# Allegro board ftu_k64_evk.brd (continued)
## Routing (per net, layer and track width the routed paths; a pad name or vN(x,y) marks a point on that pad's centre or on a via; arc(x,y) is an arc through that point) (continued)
U2_IN_N: length 36.9
  TOP w0.178: v1(34.67,52.43) 35.29,52.43 R43.2 36.49,51.23 C45.2 31.27,49.37 PT2.3 28.16,48.02 26.53,46.4 26.53,44.56 R44.2 26.58,44.53 D16.A ; R39.1 39.16,43.49 39.65,43 39.65,41.89 v1(39.75,41.78)
  BOTTOM w0.178: v1(34.67,52.43) 34.92,52.68 37.28,52.68 38.86,51.1 38.86,44.04 39.75,43.15 v1(39.75,41.78)
U2P_OUT: length 51.1
  TOP w0.305: U1.27 65.17,57.75 65.74,57.19 v1(65.74,56.52) ; C42.1 33.6,35.36 R38.2 33.58,37.13 v1(32.38,37.13)
  BOTTOM w0.305: v1(65.74,56.52) 64.92,57.33 53.89,57.33 43.91,47.35 43.91,40.86 40.18,37.13 v1(32.38,37.13)
U3_IN_N: length 47.5
  TOP w0.178: C52.2 38.17,32.41 R54.2 ; C52.2 36.23,31.94 C54.2 ; C52.2 36.23,33.23 v1(36.45,33.45) ; v1(54.33,55.5) 54.39,55.5 55.14,56.25 U1.30
  BOTTOM w0.178: v1(54.33,55.5) 54.02,55.5 45.49,46.97 45.49,40.54 38.84,33.88 36.88,33.88 v1(36.45,33.45)
U3_IN_P: length 49.3
  TOP w0.178: C52.1 35.28,31.99 35.28,31 C50.1 ; C52.1 35.28,32.83 35.28,33.45 v1(35.36,33.53) ; C52.1 R49.2 ; U1.29 63.6,56.75 63.56,56.72 54.83,56.72 v1(54.38,56.26)
  BOTTOM w0.178: v1(54.38,56.26) 54.17,56.26 45.19,47.28 45.19,40.67 38.84,34.32 36.14,34.32 v1(35.36,33.53)
UART1_RX: length 85.6
  TOP w0.127: v1(87.24,69.42) 86.91,69.75 U1.106 ; v1(96.24,68.81) 96.24,68.17 104.44,59.97 108.03,59.97 116.71,51.29 116.71,33.38 TP22.1 119.43,30.66 119.43,28.77 121.1,27.09 139.36,27.09 140.26,28 R140.1
  BOTTOM w0.127: v1(96.24,68.81) 95.83,68.4 88.26,68.4 v1(87.24,69.42)
UART1_TX: length 111.9
  TOP w0.127: R136.1 141.35,29.07 141.35,27.89 140.3,26.84 120.67,26.84 TP21.1 116.45,31.05 116.45,51.19 108,59.64 104.17,59.64 96.73,67.08 v1(96.18,67.08) ; U1.1 65.05,70.75 66.44,69.36 66.44,67.41 v1(66.09,67.06)
  BOTTOM w0.127: v1(96.18,67.08) 93.16,67.08 93.14,67.06 v1(66.09,67.06)
USB_5V: length 4.7
  TOP w0.305: U1.22 62.15,60.25 60.52,58.62 R3.1
USB_5V_HOST: length 3.1
  TOP w0.508: C80.1 142.26,113.62 U18.5
USB_EN: length 4
  TOP w0.508: TP20.1 135.16,107.49 R111.2 133.59,109.59 U17.3
USB_HOST_D_N: length 108
  TOP w0.127: v1(136.93,117.55) 137.05,117.43 L14.1 ; R10.2 58.19,62.99 57.52,63.65 56.99,63.65 v1(56.71,63.37)
  BOTTOM w0.127: v1(136.93,117.55) 136.58,117.55 136.24,117.21 136.24,114.92 107.3,85.98 107.3,84.95 106.89,84.54 100.79,84.54 85.01,68.76 62.99,68.76 57.91,63.68 57.03,63.68 56.96,63.61 v1(56.71,63.37)
USB_HOST_D_P: length 108
  TOP w0.127: L14.4 137.77,118.34 136.9,118.34 v1(136.88,118.31) ; R9.2 58.19,64.36 57.75,63.93 56.94,63.93 v1(56.74,64.14)
  BOTTOM w0.127: v1(56.74,64.14) 56.9,63.96 57.79,63.96 62.87,69.04 84.89,69.04 100.68,84.82 106.77,84.82 107.02,85.07 107.02,86.09 135.96,115.04 135.96,117.32 136.75,118.11 136.75,118.18 v1(136.88,118.31)
USB_HOST_VBUS: length 14.1
  TOP w0.508: C84.1 131.68,112.26 U17.6
  TOP w0.762: C84.1 134.55,114.26 135.61,113.21 135.61,111.99 138.22,109.37 L12.1
VOUT33: length 6.1
  TOP w0.305: C18.1 61.08,60.05 61.79,60.75 U1.21
  TOP w0.508: C17.1 C18.1
VREF_ADC: length 16.1
  TOP w0.508: C123.1 42.14,19.38 R162.1 42.14,22.17 L26.2 41.68,24.32 41.68,27.64 42.82,28.78 L10.2 44.01,28.83 44.01,30.26 L9.2 43.97,31.71 L27.2
VREF_ADC_HALF: length 29.4
  TOP w0.508: C119.1 v1(44.35,17.37) ; C119.1 v1(44.35,15.57) 44.35,14.68 C122.1 44.94,14.63 45.48,15.17 U32.7 ; C119.1 44.39,16.44 U32.6 ; v1(42.72,42.09) 42.72,42.37 43.57,43.21 R35.1 ; v1(53.65,14.43) 54.14,14.43 C120.1 54.51,15.17 U32.2 ; U6.5 v1(43,54.59) ; U32.1 52.62,13.9 53.09,13.44 C121.1 v1(54.67,12.55) ; L26.1 v1(45.29,23.01) ; R53.1 33.09,11.15 v1(33.43,10.82) ; U6.3 45.54,54.74 v1(45.33,54.53) ; R51.2 v1(35.43,10.87)
  TOP w1.016: R32.1 v1(12.89,109.52) ; TP44.1 v1(5.02,133.96) ; R30.2 v1(13.12,106.61)
VREF_HALF: length 21.9
  TOP w0.508: C123.2 45.52,18.54 46.33,17.73 46.65,17.73 U32.5 ; U32.3 53.48,16.44 53.62,16.59 C124.1
  TOP w0.762: C123.2 44.36,18.83 45.39,19.86 R162.2 46.23,19.86 R163.1 48.16,20.17 49.25,21.26 52.81,21.26 54.72,19.35 C124.1
VREF_OUT: length 38.9
  TOP w0.305: U1.37 66.13,51.3
  TOP w0.762: L9.1 58.17,30.3 59.86,32 59.86,42.24 61.72,44.09 C12.1 61.72,47.45 C11.1 61.77,48.45 62.22,48.9 62.22,50.09 63.44,51.3 66.13,51.3
VREFH: length 44.8
  TOP w0.305: U1.32 62.61,55.25 61.92,54.56 61.92,52.3 61.26,51.64 59.18,51.64 58.87,51.95 L1.1
  TOP w0.508: L1.1 57.93,52.4 57.6,52.07 57.6,51.16 57.96,50.8 C14.1 C13.1 58.95,33.27 57.04,31.37 45.69,31.37 L27.1
WAKE: length 7.3
  TOP w0.127: U12.22 108.14,97.7 107.75,98.08 R91.2 109.1,99.69 R81.1 110.49,99.7 R88.2
WDOG: length 48.8
  TOP w0.127: R147.2 113.44,25.01 R145.2 106.02,25.07 95.44,35.65 95.44,48.61 93.14,50.9 90.27,50.9 86.92,54.25 U1.75
WIFI/LCD_GPIO1: length 106.6
  TOP w0.127: v1(75.86,149.02) 73.96,147.12 73.96,140.72 75.84,138.84 75.84,113.83 62.72,100.71 62.72,78.03 56.51,71.82 56.51,68.7 57.42,67.79 62.47,67.79 63.52,66.75 U1.9
  BOTTOM w0.127: J21.13 78.96,154.1 78.96,152.12 v1(75.86,149.02)
WIFI/LCD_GPIO2: length 109.4
  TOP w0.127: J21.15 77.07,156.26 75.51,156.26 75.13,155.88 75.13,148.67 73.71,147.24 73.71,140.61 75.59,138.73 75.59,113.93 62.47,100.81 62.47,78.14 56.26,71.93 56.26,68.59 57.31,67.54 62.37,67.54 63.66,66.25 U1.10
WIFI/LCD_GPIO3: length 107.2
  TOP w0.127: U1.15 65.96,63.75 66.7,64.49 66.7,69.6 64.24,72.06 64.24,100.08 77.36,113.19 77.36,135.74 83.43,141.81 83.43,146.63 81.27,148.79 78.02,148.79 76.96,149.86 76.96,154.38 J21.17
WIFI/LCD_GPIO4: length 92.1
  TOP w0.127: U1.139 68.88,77.91 67.69,79.11 67.69,100.11 79.34,111.77 79.34,134.72 v1(79.65,135.03) ; J21.19 72.87,154 72.87,140.46 v1(74.9,138.43)
  BOTTOM w0.127: v1(74.9,138.43) 78.3,135.03 v1(79.65,135.03)
WIFI/LCD_PWR_CNTL: length 71.4
  TOP w0.127: v1(85.03,128.24) 85.03,117.1 67.94,100.01 67.94,79.91 69.34,78.51 69.34,74.37 70.38,73.33 U1.136 ; v1(91.16,129.87) 91.29,129.74 R153.2
  BOTTOM w0.127: v1(91.16,129.87) 86.66,129.87 v1(85.03,128.24)
N16756265: length 3
  TOP w0.127: R65.1 T1.10
N16756269: length 3.3
  TOP w0.127: R66.1 137.7,69.23 137.21,68.73 T1.15
N16757442: length 16.4
  TOP w0.305: D11.A 142.6,39.2 142.2,38.8 R135.2 ; D11.A 146.72,40.79 DN2.1 ; D11.A 147.47,36.86 147.47,34.98 148.67,33.77 J16.2
N16757516: length 15.9
  TOP w0.305: D10.A 146.29,28.47 DN1.1 ; J16.3 146.85,31.03 DN1.1 ; DN1.1 145.1,31.65 145.1,32.38 144.5,32.99 142.98,32.99 R139.2
N16758787: length 3.4
  TOP w0.305: U28.1 125.83,39.06 125.32,39.57 C93.1
N16758791: length 5.4
  TOP w0.305: U28.3 125.71,37.76 124.81,38.66 123.54,38.66 122.74,39.46 C93.2
N16758795: length 3.5
  TOP w0.305: U28.4 125.5,37.11 124.91,37.69 C92.1
N16758815: length 5.2
  TOP w0.305: U28.5 125.18,36.46 124.81,36.83 123.44,36.83 122.69,37.58 C92.2
N16758819: length 3.4
  TOP w0.305: C91.2 124.32,35.81 U28.6
N16758823: length 4.8
  TOP w0.305: R135.1 137.88,38.8 136.84,37.76 U28.14
N16758837: length 7
  TOP w0.305: R134.2 138.6,31.56 136.37,33.79 136.37,35.28 135.84,35.81 U28.11
N16758843: length 6.7
  TOP w0.305: U28.12 135.8,36.46 136.8,35.46 136.8,33.97 137.81,32.96 R138.2
N16758849: length 4.8
  TOP w0.305: C89.1 128.56,40.37 129.1,39.83 129.1,38.63 128.88,38.41 U28.2
N16758873: length 5.1
  TOP w0.305: R139.1 137.88,35.38 136.15,37.11 U28.13
N16759319: length 2.5
  TOP w0.127: R25.1 80.22,143.73 U5.7
N16772440: length 9.4
  TOP w0.508: R28.2 48.08,56.88 U6.1 ; R28.2 48.51,60.34 R27.1 ; R28.2 51.75,60.54 D3.A
N16775214: length 11.3
  TOP w0.508: D4.A 40.66,63.3 39.04,61.68 R31.1 37.12,60.09 R33.2 38.04,58.29 38.7,58.29 40.46,56.53 U6.7
N16775930: length 19.6
  TOP w0.305: R38.1 35.2,38.44 D5.A 35.2,40.49 35.2,42.46 R40.2 34.85,44.79 34.85,47.98 35.2,48.34 38.91,48.34 40.46,49.89 U6.8
N16775968: length 6.3
  TOP w0.305: U6.10 43,49.02 43.57,48.46 R35.2 43.53,46.77 R37.2
N16775998: length 7.5
  TOP w0.305: U6.9 41.73,49.86 39.8,47.93 39.8,47.79 R39.2 38.71,46.7 R40.1
N16783367: length 15.4
  TOP w0.508: C46.2 49.05,39.46 R45.2 49.35,42.38 R47.1 49.41,44.2 C47.1 48.8,45.86 45.54,49.12 U6.12
N16785222: length 16.5
  TOP w0.762: v1(39.85,27.15) 39.77,27.23 L8.1
  BOTTOM w1.016: PT3.3 39.85,26.22 v1(39.85,27.15)
N16786136: length 2.5
  TOP w0.178: L8.2 39.77,32.38 R54.1
N16786139: length 1.8
  TOP w0.178: R49.1 L7.2
N16788483: length 15.2
  TOP w0.508: U6.13 46.81,51.54 47.24,51.96 47.95,51.96 48.08,51.84 U6.14 48.08,48.73 R46.1 52.56,45.2 53.69,44.07 D6.A
N16795804: length 1.8
  TOP w0.762: R157.1 129.52,135.55 D12.A
N16798051: length 3.9
  TOP w0.508: U17.5 132.65,111.47 132.26,111.09 C83.1
N16806806: length 4
  TOP w0.127: C77.1 118.94,80.21 R96.1 117.16,80.57 Y2.1
N16812858: length 3.2
  TOP w0.127: R2.2 81.22,49.12 81.88,49.78 U1.68
N16812861: length 3.1
  TOP w0.127: R4.2 82.38,48.52 U1.69
N16826797: length 12
  TOP w0.305: U22.4 30.17,119.98 30.17,123.06 30.45,123.34 R114.2 ; U21.2 30.28,124.12 R114.2 ; U21.3 31.55,123.83 R114.2
N16826898: length 8.7
  TOP w0.305: U23.4 34.55,122.36 33.62,123.29 R118.2 32.82,123.3 U21.4
N16826947: length 13.1
  TOP w0.508: R124.1 25.15,135.21 v1(25.12,135.18)
  BOTTOM w0.508: J12.1 36.16,134.8 25.5,134.8 v1(25.12,135.18)
N16841183: length 16.8
  TOP w0.508: R132.1 43.01,131.33 44.47,129.87 52.8,129.87 54.01,131.08 54.01,132.62 J14.1
N16842812: length 2.3
  TOP w0.127: R115.1 31.1,109.18 U22.2
N16843774: length 2.4
  TOP w0.127: R119.1 36.76,110.42 U23.2
N16843986: length 8
  TOP w0.305: U19.2 26.14,121.68 R113.2
N16846359: length 2.7
  TOP w0.305: R113.1 29.32,124.28 29.01,124.59 U21.1
N16848477: length 2.8
  TOP w0.127: U26.2 49.07,108.61 R125.1
N16848509: length 13.2
  TOP w0.305: R123.2 48.71,123.72 48.71,124.89 48.47,125.14 U25.2 ; R123.2 48.2,123.7 47.98,123.47 47.98,119.74 U26.4 ; R123.2 49.74,124.7 U25.3
N16848511: length 2.3
  TOP w0.127: R131.1 55.11,109.21 U27.2
N16848567: length 9.8
  TOP w0.305: U27.4 52.57,121.79 50.77,123.6 R130.2 50.36,124.72 51.01,125.36 U25.4
N16848581: length 9.2
  TOP w0.305: R121.2 42.79,122.12 40.68,120.01 U24.2
N16848643: length 3
  TOP w0.305: U25.1 47.2,125.11 47.25,125.06 R121.1
N16852593: length 4.7
  TOP w0.127: R143.2 116.69,17.54 117.64,18.48 U29.8
N16852608: length 21
  TOP w0.127: SW3.4 SW3.3 125.78,17.73 R142.2 125.84,17.79 C95.1 124.71,19.25 123.91,20.06 U29.1 122.03,20.06 121.37,19.39 J17.1
N16852627: length 2.9
  TOP w0.127: U29.7 116.77,21.33 116.11,21.98 R146.1
N16852920: length 3
  TOP w0.127: R147.1 115.68,23.48 116.56,22.6 U29.6
N16858143: length 6.2
  TOP w0.127: R67.1 146.29,58.08 P1.11
N16858278: length 7.3
  TOP w0.127: R68.1 143.11,72.73 P1.9
N16861702: length 3.2
  TOP w0.127: T2.10 137.05,89.53 137.3,89.29 R92.1
N16861704: length 3
  TOP w0.127: T2.15 135.57,95.79 R93.1
N16871213: length 6.4
  TOP w0.305: L22.1 103.89,129.93 Q3.2 102.35,127.63 L20.1 100.14,127.53 R149.1
N16871247: length 4.1
  TOP w0.305: R153.1 92.68,127.52 R155.1 94.11,127.54 Q5.1
N16871250: length 9.4
  TOP w0.305: C100.2 98.56,128.5 98.51,128.45 R149.2 ; C100.2 97.61,129.95 96.82,130.73 96.82,132.21 R151.1 ; C100.2 98.58,129.93 Q3.1
N16871668: length 2.1
  TOP w0.305: Q5.3 94.14,132.47 R151.2
N16872241: length 4.7
  TOP w0.305: R154.1 110.44,129.71 Q6.1 110.44,129.7 R156.1
N16872243: length 9.7
  TOP w0.305: R150.2 116.54,129.07 Q4.1 114.69,129.24 C102.2 113.9,129.53 113.6,129.83 113.6,132.03 R152.1
N16872250: length 5.2
  TOP w0.305: R150.1 118.14,129.11 Q4.2 120.08,129.24 L21.1 121.55,129.24 L23.1
N16872280: length 2.5
  TOP w0.305: Q6.3 110.15,133.14 R152.2
N16877055: length 2.9
  TOP w0.508: U30.1 115.7,116.4 R159.2
N16877530: length 3.8
  TOP w0.508: R160.2 122.01,116.78 119.76,114.54 U30.8
N16877846: length 1.6
  TOP w0.508: C111.1 123.59,116.94 R160.1
N16878713: length 4.7
  TOP w0.508: U30.7 120.75,113.27 121.39,113.9 R158.1 122.14,113.97 R161.2
N16899253: length 7
  TOP w0.305: R97.1 115.99,83.32 114.09,85.22 U12.1
N16906260: length 7
  TOP w0.127: R94.1 144.43,86.98 P2.11
N16913941: length 3.7
  TOP w0.127: R84.2 103.69,90.21 104.35,90.87 U12.31
N16913953: length 4
  TOP w0.127: R85.2 103.34,93.23 104.69,91.87 U12.29
N16913968: length 4.3
  TOP w0.127: R86.2 102.45,94.57 104.65,92.37 U12.28
N16913982: length 5.4
  TOP w0.127: R87.2 102.83,95.97 103.32,95.48 103.32,94.28 104.73,92.87 U12.27
N16913996: length 5.9
  TOP w0.127: R89.2 103.73,95.84 103.73,94.56 104.91,93.37 U12.26
N16917794: length 5.5
  TOP w0.127: U1.74 86.78,53.75 89.34,51.19 R11.1
N16918817: length 6.4
  TOP w0.127: R12.1 68.36,44.88 68.36,49.91 68.38,49.93 U1.41
N16919212: length 2.6
  TOP w0.127: Y1.1 87.65,43.91 R16.2
N16919504: length 2.4
  TOP w0.127: Y1.3 92.73,47.66 R18.1
N16920348: length 5.2
  TOP w0.127: R9.1 62.92,61.75 U1.19
N16920352: length 4.8
  TOP w0.127: U1.20 62.05,61.25 R10.1
N16922932: length 1.6
  TOP w0.305: R99.1 102.51,78.49 D8.C
N16922934: length 2.3
  TOP w0.305: R99.2 104.09,77.81 Q1.3
N16922936: length 1.9
  TOP w0.305: R101.1 100.09,74.43 Q1.1
N16922944: length 2.2
  TOP w0.305: Q2.3 98.18,77.59 R100.2
N16922946: length 1.7
  TOP w0.305: D9.C 96.58,80.12 R100.1
N16922998: length 2.2
  TOP w0.127: R106.1 60.88,109.09 U15.2
N16923008: length 51.9
  TOP w0.305: J8.2 48.93,155.19 48.25,154.5 R104.2 48.91,152.5 55.8,152.5 61.13,147.17 61.13,138.05 56.84,133.76 56.84,122.79 58.34,121.28 U15.4
N16923020: length 44.4
  TOP w0.305: U15.3 60.88,120.95 58.11,123.72 58.11,134.16 61.56,137.62 61.56,148.06 55.28,154.34 R108.1 54.4,154.53 53.75,155.19 J8.1
N16923032: length 3.3
  TOP w0.127: R105.1 65.66,108.54 66.65,109.52 U16.2
N16923042: length 43.7
  TOP w0.305: U16.4 64.11,119.83 58.54,125.4 58.54,132.41 62.2,136.07 62.2,148.97 58.86,152.31 R103.2 60.34,154.25 J9.2
N16923054: length 44.3
  TOP w0.305: U16.3 66.65,118.87 59.66,125.86 59.66,132.11 62.66,135.1 62.66,146.81 66.15,150.31 R107.1 65.43,154.37 64.75,155.06 J9.1
N16935990: length 1.7
  TOP w0.508: R34.1 16.57,116.64 L6.2
N16935992: length 1.7
  TOP w0.508: L5.2 18.09,99.66 R29.1
N16963015: length 2.5
  TOP w0.127: TP12.1 99.41,97.37 R89.1
N16963035: length 2.3
  TOP w0.127: R84.1 99.23,90.21 TP9.1
N16963490: length 2.6
  TOP w0.127: TP10.1 100.12,93.23 R85.1
N16963499: length 2.4
  TOP w0.127: R86.1 99.82,93.74 TP8.1
N16963508: length 2.2
  TOP w0.127: TP11.1 98.65,95.97 R87.1
N16964483: length 6.7
  TOP w0.127: R143.1 113.32,16.77 113.81,16.28 118.28,16.28 J17.2
N16992640: length 4.7
  TOP w0.127: R13.2 60.68,71.5 62.43,69.75 U1.3
N16997663: length 8.6
  TOP w0.305: U28.9 134.28,31.38 136.89,28.77 R140.2
N16997666: length 7.5
  TOP w0.305: U28.10 135.42,35.16 135.73,34.85 135.73,33.08 R136.2
N17002202: length 4.1
  TOP w0.127: TP18.1 69.31,9.28 J10.15
N17002209: length 9
  TOP w0.127: TP17.1 75.61,9.26 73.6,9.26 72.28,7.94 72.28,6.36 J10.14
N17002232: length 7
  TOP w0.127: TP19.1 70.33,8.14 70.33,6.4 J10.16
N17002285: length 2.7
  TOP w0.127: TP27.1 109.92,155.26 J22.11
N17002298: length 2.7
  TOP w0.127: TP28.1 107.96,155.21 J22.13
N17002307: length 2.7
  TOP w0.127: J22.15 105.93,155.25 TP30.1
N17009409: length 4.4
  TOP w0.508: U7.7 57.67,6.64 R55.1 57.82,6.49 57.82,4.62 D7.A
N17012939: length 5.8
  TOP w0.305: U28.7 125.45,35.16 123.64,33.35 R137.1
N17012953: length 9
  TOP w0.305: U28.8 127.32,29.66 126.24,28.58 R141.1
N17025356: length 4.5
  TOP w0.305: U20.4 62.94,128.12 L15.1
N17038152: length 2.5
  TOP w0.127: U2.8 108.79,42.95 R14.1
N17038155: length 2.5
  TOP w0.127: U2.7 110.06,43.23 R15.1
N17041648: length 2.9
  TOP w0.127: TP31.1 78.1,150.44 J21.16
N17041650: length 2.9
  TOP w0.127: J21.14 80.1,150.37 TP29.1
N17041652: length 2.9
  TOP w0.127: J21.10 84.1,151.75 84.06,151.71 TP26.1
N17041654: length 2.8
  TOP w0.127: TP25.1 92.1,150.49 J21.2
N17042189: length 3.5
  TOP w0.127: R148.1 105.97,153.2 J22.16
N17042264: length 2.6
  TOP w0.127: J22.17 104,155.24 TP34.1
N17042273: length 2.6
  TOP w0.127: J22.19 101.97,155.21 TP35.1
N17042288: length 2.8
  TOP w0.127: J22.18 103.96,151.91 103.92,151.87 TP36.1
N17042303: length 2.8
  TOP w0.127: J22.20 101.96,151.96 101.89,151.88 TP37.1
N17042405: length 2.8
  TOP w0.127: J21.18 76.1,150.43 TP38.1
N17042414: length 2.8
  TOP w0.127: J21.20 74.05,153.19 TP39.1
N17045351: length 3.8
  TOP w0.127: TP40.1 67.31,9.97 J10.17
N17045355: length 4.8
  TOP w0.127: J10.19 62.06,10.63 TP41.1
N17045369: length 6.1
  TOP w0.127: J10.18 68.3,6.37 68.3,10.43 TP42.1
N17045378: length 6.6
  TOP w0.127: J10.20 66.19,6.26 66.19,8.83 TP43.1
N17061950: length 1.9
  TOP w0.305: Q2.1 94.57,74.48 R102.1
N17108951: length 28.3
  TOP w0.508: C65.1 147.17,75.2 v1(147.04,75.06) ; R66.2 140.24,69.27 v1(141.24,69.27) ; R65.2 v1(140.18,61.16)
  BOTTOM w0.508: v1(147.04,75.06) v1(141.24,69.27) 136.16,69.27 135.7,68.81 135.7,63.81 138.35,61.16 v1(140.18,61.16)
N17109053: length 28.6
  TOP w0.508: v1(146.86,101.63) 146.97,101.74 C76.1 ; R93.2 v1(140.05,96.68)
  TOP w0.762: R92.2 v1(141.31,89.29)
  BOTTOM w0.508: v1(141.31,89.29) 137.02,89.29 135.66,90.65 135.66,95.83 136.5,96.68 v1(140.05,96.68) 141.91,96.68 v1(146.86,101.63)
N17166355: length 3
  TOP w0.305: R75.1 R76.1 120.44,91.66 C125.1
N17166431: length 3.2
  TOP w0.305: C126.1 120.73,88.92 R78.1 118.9,88.89 R77.1
N17167419: length 5.3
  TOP w0.127: J10.13 73.71,9.78 74.19,9.78 TP45.1
N17171737: length 4.8
  TOP w0.127: U1.38 66.88,50.65 66.63,50.4 64.44,50.4 TP46.1
N17171740: length 3.3
  TOP w0.127: TP47.1 66.14,50.15 66.84,50.15 67.38,50.68 U1.39
N17171751: length 4.2
  TOP w0.127: U1.35 62.87,53.75 62.26,53.14 62.26,51.47 TP48.1
N17171755: length 2.3
  TOP w0.127: TP49.1 62.9,57.59 63.56,58.25 U1.26

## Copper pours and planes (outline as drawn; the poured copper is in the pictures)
5V_DC_JACK on TOP: 144.7,144.88 148.31,144.88 149.3,143.89 149.3,137.54 147.57,135.81 140.08,135.81 137.21,138.68 135.78,138.68 135.38,139.09 135.38,141.15 135.94,141.71 141.52,141.71
5V_IN on TOP: 131.31,145.01 138.58,145.01 138.98,144.6 138.98,142.65 138.42,142.09 135.63,142.09 134.84,141.3 134.84,138.71 135.17,138.38 135.17,137.06 135.15,137.03 132.38,137.03 132.1,136.75 130.78,136.75 130.65,136.88 130.65,144.35
AGND on BOTTOM: 0.94,159.05 66.16,159.05 67.11,158.11 67.11,117.66 66.24,116.8 22.85,116.8 21.84,117.81 21.84,133.95 16.79,139 1.05,139 0.8,139.24 0.8,158.92
AGND on GND: 16.64,138.91 0.76,138.91 0.76,159.24 67.23,159.24 67.23,120.96 67.33,120.85 67.33,117.68 66.24,116.59 21.89,116.59 21.89,133.66
GND on TOP: 130.63,152.63 148.03,152.63 154.27,146.38 154.27,138.84 153.46,138.02 151.96,138.02 150.59,139.4 150.59,144.48 149.4,145.67 144.17,145.67 141.47,142.98 140.2,142.98 139.64,143.54 139.64,144.78 138.15,146.28 130.96,146.28 128.87,148.36 128.87,150.88
GND on TOP: 113.15,113.74 114.8,113.74 115.41,114.35 117.7,114.35 117.83,114.22 117.83,107.9 117.37,107.44 113.13,107.44 112.47,108.1 112.47,110.57 112.95,111.05 114.8,111.05 115.11,111.35 115.11,112.62 114.78,112.95 113.08,112.95 113,113.03 113,113.59
GND on BOTTOM: 67.97,158.98 148.89,158.98 150.33,157.54 150.33,152.6 154.06,148.87 154.06,139.18 153.38,138.51 148.22,138.51 145.51,135.8 145.51,105.19 141.74,101.42 128.77,101.42 126.96,99.61 126.96,59.13 127.42,58.68 136.24,58.68 136.84,59.28 140.76,59.28 147.85,52.19 147.85,36.66 151.24,33.27 151.24,23.85 148.45,21.06 148.45,15.52 150.22,13.75 150.22,10.2 149.58,9.56 148.33,9.56 148.3,9.6 146.71,9.6 142.19,5.08 88.33,5.08 86.33,7.07 86.33,11.3 86.71,11.67 86.71,20.84 78.6,28.94 78.6,47.6 77.13,49.06 69.82,49.06 68.05,50.84 68.05,57.96 65.26,60.75 61.61,60.75 60.7,59.84 56.93,59.84 47.39,69.38 47.39,90.3 48.07,90.98 52.1,90.98 52.97,91.84 52.97,95.42 51.05,97.35 46.79,97.35 42.49,101.64 28.36,101.64 22.06,107.94 22.06,115.06 22.59,115.59 66.77,115.59 67.97,116.8 ; 19 cut-outs
GND on GND: 63.04,0.76 63.04,47.39 63.78,48.13 65.53,48.13 67.94,50.54 67.94,57.79 65.43,60.3 62.3,60.3 61.43,59.44 57.05,59.44 47.19,69.29 47.19,96.8 42.7,101.3 28.4,101.3 21.84,107.85 21.84,116.08 66.92,116.08 67.92,117.07 67.92,159.01 68.15,159.24 159.24,159.24 159.24,0.76
GND_EARTH on TOP: 151.73,158.47 157.58,158.47 159.05,157 159.05,2.69 157.47,1.12 153.49,1.12 153.46,1.14 1.99,1.14 0.89,2.24 0.89,5.86 2.4,7.37 5.36,7.37 8.74,4 11.9,4 12.6,3.29 83.61,3.29 84.77,4.45 123.88,4.45 124.55,3.78 148.65,3.78 152.29,7.43 152.29,13.46 149.32,16.43 149.32,20.52 154.66,25.86 154.66,37.64 150.39,41.91 150.39,54.1 154.17,57.89 154.17,67.11 152.57,68.71 151.51,68.71 150.13,70.08 150.13,81.94 154.25,86.06 154.25,94.44 152.83,95.86 151.48,95.86 150.44,96.9 150.44,105.61 148.74,107.31 148.74,111.81 150.13,113.21 150.13,121.64 148.28,123.49 148.28,131.78 155.09,138.58 155.09,147.27 150.36,151.99 150.36,157.1
GND_EARTH on BOTTOM: 146.36,8.57 150.56,8.57 151.28,9.28 151.28,15.37 149.69,16.95 149.69,20.42 155.27,25.99 155.27,36.44 149.43,42.28 149.43,54.72 154.97,60.26 154.97,65.8 150.18,70.58 150.18,81.89 153.35,85.06 153.91,85.06 154.48,85.62 154.48,94.03 152.63,95.88 151.54,95.88 148.11,99.31 148.11,111.52 149.73,113.14 149.73,121.88 148.9,122.71 148.9,136.25 150.33,137.68 153.88,137.68 155.08,138.89 155.08,149.48 151.05,153.51 151.05,157.69 151.95,158.6 157.64,158.6 158.92,157.31 158.92,1.34 158.52,0.94 2.12,0.94 1.03,2.03 1.03,6.39 2.05,7.41 6.27,7.41 7.96,5.72 7.96,4.95 9.05,3.86 88.19,3.86 88.68,4.35 142.14,4.35
GND_EARTH on VCC: 152.06,0.76 152.06,13.14 149.68,15.52 149.68,20.82 154.58,25.73 154.58,37.67 150.06,42.19 150.06,51.87 147.78,54.15 139.47,54.15 133.55,60.07 133.55,97.99 134.59,99.03 143.64,99.03 148.74,104.14 148.74,111.91 150.08,113.26 150.08,121.42 148.28,123.22 148.28,131.57 155.26,138.55 155.26,147.53 150.49,152.3 150.49,159.24 159.24,159.24 159.24,0.76
GNDA on VCC: 0.76,0.76 0.76,138.43 16.5,138.43 21.28,133.65 21.28,107.69 28.19,100.79 42.49,100.79 46.68,96.59 46.68,69.42 46.65,69.42 46.65,69.11 56.84,58.93 61.64,58.93 62.51,59.79 65.22,59.79 67.43,57.58 67.43,50.54 65.53,48.64 63.57,48.64 62.53,47.6 62.53,0.76
GNDA on GND: 0.76,0.76 0.76,138.4 16.42,138.4 21.25,133.58 21.25,107.72 28.19,100.79 42.49,100.79 46.68,96.59 46.68,69.08 56.84,58.93 61.64,58.93 62.51,59.79 65.22,59.79 67.43,57.58 67.43,50.75 65.32,48.64 63.57,48.64 62.53,47.6 62.53,0.76
VCC_3V3 on TOP: 51.12,101.27 55.6,101.27 56.1,100.76 56.1,91.49 55.24,90.63 55.24,86.77 54.91,86.44 53.61,86.44 53.08,86.97 53.08,91.16 50.9,93.34 50.9,101.04
VCC_3V3 on BOTTOM: 47.34,95.55 51.89,95.55 52.22,95.22 52.22,92.1 51.94,91.82 47.75,91.82 46.88,92.68 46.88,95.1
VDD_3V3 on TOP: 102.56,121.26 106.62,121.26 107.34,120.55 107.34,119.38 106.37,118.41 106.37,109.91 105.89,109.42 102.89,109.42 100.93,111.38 100.93,119.63
VDD_3V3 on VCC: 63.04,0.76 63.04,47.39 63.78,48.13 65.53,48.13 67.94,50.54 67.94,57.79 65.43,60.3 62.3,60.3 61.43,59.44 57.05,59.44 47.19,69.29 47.19,96.8 42.7,101.3 28.4,101.3 21.79,107.9 21.79,116.08 66.6,116.08 67.81,117.29 67.81,159.24 149.98,159.24 149.98,152.09 154.76,147.32 154.76,138.76 147.77,131.78 147.77,123.01 149.58,121.21 149.58,113.47 148.23,112.12 148.23,104.35 143.42,99.54 129.99,99.54 128.06,97.62 128.06,90.47 129.18,89.35 129.18,86.87 127.86,85.55 127.86,63.47 128.9,62.43 128.9,59.1 129.79,58.22 134.69,58.22 139.26,53.64 147.57,53.64 149.55,51.66 149.55,41.98 154.07,37.46 154.07,25.94 149.17,21.03 149.17,15.31 151.56,12.93 151.56,0.76
VDD_5V on TOP: 118.66,112.39 121.41,112.39 121.69,112.67 122.7,112.67 123.18,112.19 123.18,109.42 123.85,108.76 125.27,108.76 125.78,109.27 125.78,122.17 124.61,123.34 109.19,123.34 105.66,126.87 105.66,127.79 105.08,128.37 105.08,130.23 104.57,130.73 103.28,130.73 102.95,131.06 102.95,133.45 103.71,134.21 106.22,134.21 106.88,133.55 106.88,128.98 110.57,125.3 122.63,125.3 123.24,125.91 123.24,130.05 123.27,130.07 121.43,130.07 121.13,130.38 121.13,131.42 121.71,132 131.82,132 133.45,133.63 133.45,136.25 133.75,136.55 136.98,136.55 137.31,136.22 137.31,129.31 128.83,120.83 128.83,110.54 129.16,110.21 129.94,110.21 129.97,110.24 131.8,110.24 132,110.03 132,109.73 131.97,109.7 131.97,109.02 132.2,108.79 132.2,106.96 120.77,106.96 118.31,109.42 118.31,112.04
VDD_5V on TOP: 66.17,130.23 70.51,130.23 73.3,127.43 73.3,112.22 61.93,100.84 61.93,88.87 60.78,87.73 58.19,87.73 57.38,86.92 56.21,86.92 55.91,87.22 55.91,90.14 57.48,91.72 59.49,91.72 59.82,92.05 59.82,101.37 68.73,110.29 68.73,122.35 65.2,125.88 65.2,127.86 65.91,128.57 65.91,129.97
VDDA_3V3 on TOP: 42.74,95.02 46.27,95.02 46.68,94.61 46.68,72.92 39.11,65.35 36.65,65.35 35.99,66.01 35.99,68.71 42.16,74.88 42.16,94.44
VDDA_3V3 on TOP: 49.22,56.34 52.73,56.34 53.51,55.55 53.51,52.3 52.78,51.56 50.31,51.56 49.04,52.83 49.04,56.16
VDDA_3V3 on BOTTOM: 36.39,66.73 40.84,66.73 50.41,57.15 50.41,54.91 49.55,54.05 47.7,54.05 46.53,55.22 46.53,56.64 45.77,57.4 42.03,57.4 35.91,63.53 35.91,66.24
VDDA_3V3 on BOTTOM: 57.45,55.91 62.43,55.91 62.78,55.55 62.78,46.63 60.7,44.55 52.5,44.55 51.76,43.81 51.76,42.37 52.29,41.83 66.09,41.83 66.8,41.12 66.8,18.54 58.54,10.29 58.54,7.71 57.93,7.09 54.28,7.09 53.77,7.6 53.77,8.86 58.64,13.74 58.64,18.67 57.22,20.09 50.34,20.09 50.15,19.9 50.15,14.32 46.97,11.14 45.35,11.14 45.05,11.44 45.05,13.29 46.64,14.88 46.64,23.33 47.04,23.72 47.04,47.62 55.24,55.83 57.37,55.83
DC_V1_IN on TOP: 47.11,38.66 48.2,37.57 51.66,37.57 52.78,36.45 52.78,32.66 52.19,32.08 46.88,32.08 45.23,33.73 45.23,35.28 44.87,35.65 42.9,35.65 42.56,35.98 42.56,37.84 43.38,38.66
RS485_5V on VCC: 21.79,116.59 21.79,116.59 21.79,133.86 16.71,138.94 0.76,138.94 0.76,159.24 67.3,159.24 67.3,117.5 66.39,116.59
U1_L on TOP: 33.01,71.07 30.58,71.07 22.4,79.25 22.4,80.77 21.33,81.84 14.96,81.84 13.51,80.39 2.72,80.39 1.39,81.72 1.39,83.77 1.63,84 23.86,84 28.1,79.77 28.1,79.09 29.25,77.94 31.45,77.94 33.91,75.48 33.91,71.97
U1_N on TOP: 6.22,96.39 20.9,96.39 22.8,94.5 22.8,86.43 21.31,84.94 1.61,84.94 1.32,85.24 1.32,94.51 3.18,96.38 6.2,96.38
U2_L on TOP: 6.16,55.33 7.33,54.16 15.84,54.16 17.69,52.31 17.69,45.19 20.64,42.24 32.79,42.24 33.32,41.71 33.32,39.1 32.83,38.6 15.08,38.6 1.14,52.54 1.14,55.24 1.23,55.33
U2_N on TOP: 1.77,65.06 18.86,65.06 21.08,62.84 21.08,56.85 19.22,55 10.48,55 9.19,56.29 1.28,56.29 1.04,56.52 1.04,64.33
U3_L on TOP: 3.23,21.78 3.49,21.52 11.34,21.52 11.41,21.58 13.86,21.58 15.48,19.96 15.48,11.78 21.18,6.09 39.26,6.09 39.59,5.76 39.59,4.27 39.32,4 16.54,4 7.4,13.14 2.77,13.14 0.93,14.98 0.93,21.17 1.53,21.78
U3_N on TOP: 1.44,32.68 18.06,32.68 20.51,30.23 20.51,24.6 18.26,22.35 3.92,22.35 3.49,22.78 1.57,22.78 1.01,23.34 1.01,32.25
USB_5V_HOST on TOP: 141.9,115.04 148.86,115.04 149.09,114.81 149.09,113.39 144.55,108.84 141.98,108.84 141.85,108.97 141.85,111.81 141.29,112.37 141.29,114.43
VREF_1V2 on TOP: 46.27,29.72 48.08,29.72 48.48,29.31 48.48,26.8 47.9,26.21 43,26.21 42.84,26.37 42.84,27.79 43.15,28.09 44.55,28.09 44.83,28.37 44.83,29.34 44.98,29.49 46.04,29.49
VREF_ADC_HALF on BOTTOM: 5.08,135.28 12.36,135.28 12.85,134.8 12.85,127.74 10.28,125.17 10.28,119.84 16,114.12 16,91.41 20.45,86.96 25.55,86.96 31.83,80.68 31.83,77.16 29.8,75.12 29.8,71.1 33.16,67.75 33.16,63.89 40.51,56.54 45.69,56.54 45.77,56.46 45.77,53.31 45.36,52.91 38.78,52.91 35.06,56.63 30,56.63 27.91,54.53 27.91,47.95 29.94,45.92 33.14,45.92 38.53,40.54 40.46,40.54 41.14,41.22 41.14,43.05 41.6,43.51 42.74,43.51 43.1,43.15 43.1,40.51 40.36,37.77 36.22,37.77 33.1,40.88 30.86,40.88 30.86,40.89 30.29,40.89 28,38.61 28,14.7 28.73,13.97 31.01,13.97 40.68,23.65 45.3,23.65 45.73,23.21 45.73,15.83 43.96,14.05 43.96,11.52 44.73,10.74 48.92,10.74 51.94,13.75 51.94,17.5 53.69,19.25 56.74,19.25 57.22,18.77 57.22,14.45 49.75,6.99 25.66,6.99 21.53,11.11 21.53,71.54 22.8,72.8 22.8,79.78 21.53,81.04 19.5,81.04 11.44,89.1 11.44,113.69 5.01,120.13 5.01,130.44 4.51,130.93 4.51,134.72
N16785222 on TOP: 26.84,17.38 30.22,17.38 30.91,16.68 30.91,11.48 30.28,10.86 30.28,9.55 30.12,9.38 26.91,9.38 26.46,9.83 26.46,17
N16785246 on BOTTOM: 9.89,18.19 19.69,18.19 20.65,17.23 20.65,6.79 18.1,4.24 9.52,4.24 9.09,4.67 9.09,17.39
N16785292 on TOP: 21.34,33.44 27.85,33.44 28.33,32.96 28.33,31.25 29.06,30.52 31.88,30.52 40.12,22.28 40.12,11.15 39.75,10.79 37.77,10.79 36.91,11.65 36.91,16.52 33.46,19.96 27.14,19.96 25.15,17.97 25.15,11.52 24.95,11.32 23.26,11.32 21.97,12.61 21.97,30.36 20.41,31.92 20.41,32.51
N16878286 on TOP: 108.96,116.23 111.65,116.23 112.44,115.44 112.44,113.08 112.9,112.62 114.42,112.62 114.73,112.32 114.73,111.73 114.55,111.56 113,111.56 110.56,109.12 109.04,109.12 108.45,109.7 108.45,115.72
N16932299 on BOTTOM: 1.74,49.98 19.8,49.98 20.81,48.97 20.81,47.21 11.89,38.29 1.64,38.29 1,38.93 1,49.24
N16932357 on TOP: 22.27,66.04 24.23,66.04 24.67,65.6 24.67,43.8 24.32,43.46 22.31,43.46 21.76,44 21.76,65.53
N16935752 on TOP: 8.25,115.72 16.86,115.72 17.27,115.32 17.27,112.93 17.98,112.22 17.98,111.1 17.75,110.87 8.4,110.87 7.01,112.27 7.01,114.48
N16935822 on TOP: 7.94,104.55 17.52,104.55 18.03,104.04 18.03,102.57 17.14,101.68 17.14,100.79 16.83,100.48 8.73,100.48 7.08,102.13 7.08,103.68
N167792300 on TOP: 11.81,75.06 7.36,70.61 2.59,70.61 1.01,72.19 1.01,78.29 2.14,79.42 14.67,79.42 15.69,80.43 20.7,80.43 21.06,80.07 21.06,77.48 18.64,75.06

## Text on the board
Board Geometry/Soldermask Bottom: 8 OF 10 | SECONDARY SOLDERMASK
Package Geometry/Pastemask Bottom: 10 OF 10 | SECONDARY PASTEMASK
Ref Des/Silkscreen Bottom: COIL2 | 2013/01/08 | CSC0411V1.2A1 | COIL1 | GND | 3V3 | BKGD | RST | 5V- | 5V+ | 9 OF 10 | SECONDARY SILKSCREEN
Board Geometry/Soldermask Top: 3 OF 10 | PRIMARY SOLDERMASK
Package Geometry/Pastemask Top: 1 OF 10 | PRIMARY PASTEMASK
Ref Des/Silkscreen Top: DC-AOUT | DC-AIN | DC-VIN | GND | STATUS2 | ADC_IN | STATUS1 | 3.3V | UART-RX | UART-TX | 232-RX | 232-TX | WDOG | GPIO_IN1 | GPIO_IN2 | POWER | 2 OF 10 | PRIMARY SILKSCREEN
DIMENSION: PRIMARY DATUM | GRID ORIGIN | PCB THICKNESS = 1.6MM
BODY_CENTER: 16. | 8
User.8: FIGURE | SIZE | 12.0 | 14.0 | 32.0 | 36.0 | 40.0 | 44.0 | 55.0 | 63.0 | 74.0 | 95.0 | 125.0 | 139.0 | 128.0 | 158.0x40.0 | 178.0x40.0 | DRILL CHART: TOP to BOTTOM | ALL UNITS ARE IN MILS | TOLERANCE | +2.0/-2.0 | +0.0/-0.0 | +3.0/-3.0 | PLATED | NON-PLATED | QTY | 540 | 2 | 60 | 48 | 26 | 65 | 14 | 7 | 4 | 1
